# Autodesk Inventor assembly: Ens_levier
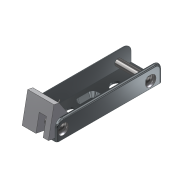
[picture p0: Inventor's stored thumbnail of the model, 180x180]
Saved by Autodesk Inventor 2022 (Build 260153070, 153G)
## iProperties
Created: 2018-06
Part Number: Ens_levier
Material: Générique
Document SubType Name: Assembly
Designer: Fabian Perrée
Mass: 50.2616 g
Surface Area: 113.894 cm^2
Volume: 10.4343 cm^3
Author: Fabian Perrée
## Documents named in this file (6)
- C:\Users\Fabian\Google Drive\01_Giup\01_Clients\07_ENI\Manuscrit\Fichiers_exercice\Capteur\Ens_levier\Ens_levier.iam
- C:\Users\Fabian\Google Drive\01_Giup\01_Clients\07_ENI\Manuscrit\Fichiers_exercice\Capteur\Ens_levier\Composants\Levier.ipt
- C:\Users\Fabian\Google Drive\01_Giup\01_Clients\07_ENI\Manuscrit\Fichiers_exercice\Capteur\Ens_levier\Composants\Butee.ipt
- C:\Users\Fabian\Google Drive\01_Giup\01_Clients\07_ENI\Manuscrit\Fichiers_exercice\Capteur\Ens_levier\Composants\Axe_25.ipt
- C:\Users\Fabian\Google Drive\01_Giup\01_Clients\07_ENI\Manuscrit\Fichiers_exercice\Capteur\Ens_levier\Composants\Axe_28.ipt
- C:\Users\Fabian\Google Drive\01_Giup\01_Clients\07_ENI\Manuscrit\Fichiers_exercice\Capteur\Ens_levier\Design Accelerator\Ressort de torsion1.iam
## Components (5 placed, 5 different names)
1. Levier:1 — Placage:4, Logement:2
2. Butee:1 — Tangente:1, Tangente:2
3. Axe_25:1 — Placage:3
4. Axe_28:1 — Logement:2
5. Ressort de torsion:1 [sub-assembly] — Placage:3, Tangente:1, Tangente:2, Placage:4
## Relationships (5: Mate 2, Tangent 2, Insert 1)
- Placage:3 [Mate]: Axe_25:1 ↔ Ressort de torsion:1
- Tangente:1: Butee:1 ↔ Ressort de torsion:1
- Tangente:2: Butee:1 ↔ Ressort de torsion:1
- Placage:4 [Mate]: Levier:1 ↔ Ressort de torsion:1
- Logement:2 [Insert]: Levier:1 ↔ Axe_28:1
